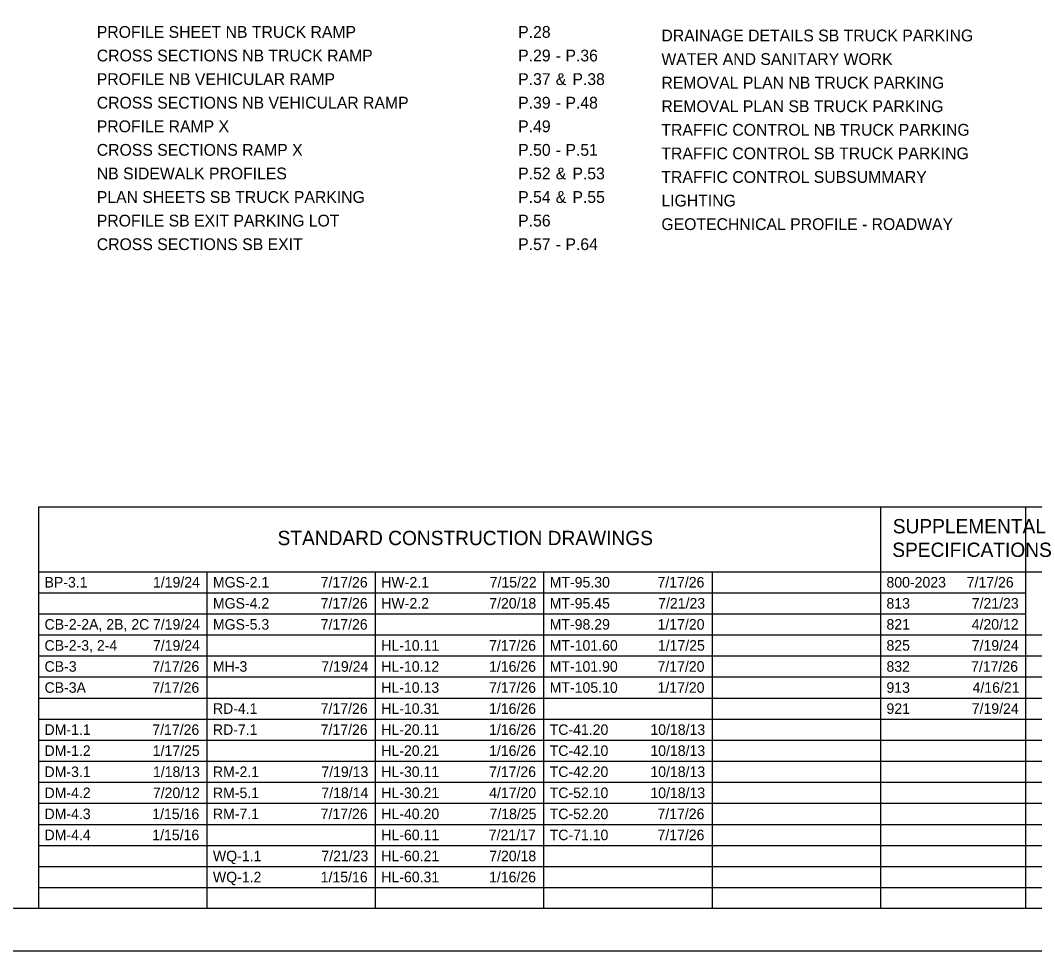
# Model space of a CAD drawing. Extents: x 0 to 34, y 0 to 22.
# Drawn here: x 9.93 to 21.98, y 0 to 11.05 of the extents above; entities that cross this region are included whole.
import ezdxf

# ---------------------------------------------------------------- set-up
doc = ezdxf.new("R2010")
doc.units = 0
for name, color, linetype in [('SH_Border', 7, 'Continuous'), ('SH_Cut_Line', 7, 'Continuous'), ('SH_Data', 7, 'Continuous'), ('SH_Text', 7, 'Continuous')]:
    doc.layers.add(name, color=color, linetype=linetype)

msp = doc.modelspace()

# ---------------------------------------------------------------- linework, layer by layer
at = {"layer": 'SH_Border'}
msp.add_lwpolyline([(1.5, 21.5), (33.5, 21.5), (33.5, 0.5), (1.5, 0.5)], close=True, dxfattribs=at)
at = {"layer": 'SH_Cut_Line'}
msp.add_lwpolyline([(0, 0), (34, 0), (34, 22), (0, 22)], close=True, dxfattribs=at)
at = {"layer": 'SH_Data'}
for p, q in [((10.15, 5.271), (23.6, 5.271)), ((10.15, 0.5), (10.15, 5.271)), ((20.15, 0.5), (20.15, 5.271)), ((21.875, 0.5), (21.875, 5.271)), ((10.15, 4.5), (23.6, 4.5)), ((12.15, 0.5), (12.15, 4.5)), ((14.15, 0.5), (14.15, 4.5)), ((16.15, 0.5), (16.15, 4.5)), ((18.15, 0.5), (18.15, 4.5)), ((10.15, 4.25), (21.875, 4.25)), ((10.15, 4), (21.875, 4)), ((10.15, 3.75), (23.6, 3.75)), ((10.15, 3.5), (23.6, 3.5)), ((10.15, 3.25), (23.6, 3.25)), ((10.15, 3), (23.6, 3)), ((10.15, 2.75), (23.6, 2.75)), ((10.15, 2.5), (23.6, 2.5)), ((10.15, 2.25), (23.6, 2.25)), ((10.15, 2), (23.6, 2)), ((10.15, 1.75), (23.6, 1.75)), ((10.15, 1.5), (23.6, 1.5)), ((10.15, 1.25), (23.6, 1.25)), ((10.15, 1), (23.6, 1)), ((10.15, 0.75), (23.6, 0.75))]:
    msp.add_line(p, q, dxfattribs=at)

# ---------------------------------------------------------------- texts
at = {"layer": 'SH_Text'}
for s, height, p in [('PROFILE SHEET NB TRUCK RAMP', 0.14, (10.839, 10.838)), ('P.28', 0.14, (15.844, 10.838)), ('DRAINAGE DETAILS SB TRUCK PARKING', 0.14, (17.545, 10.796)), ('CROSS SECTIONS NB TRUCK RAMP', 0.14, (10.839, 10.558)), ('P.29', 0.14, (15.844, 10.558)), (' - ', 0.14, (16.238, 10.558)), ('P.36', 0.14, (16.405, 10.558)), ('WATER AND SANITARY WORK', 0.14, (17.545, 10.516)), ('PROFILE NB VEHICULAR RAMP', 0.14, (10.839, 10.278)), ('P.37', 0.14, (15.844, 10.278)), (' & ', 0.14, (16.238, 10.278)), ('P.38', 0.14, (16.488, 10.278)), ('REMOVAL PLAN NB TRUCK PARKING', 0.14, (17.545, 10.236)), ('CROSS SECTIONS NB VEHICULAR RAMP', 0.14, (10.839, 9.998)), ('P.39', 0.14, (15.844, 9.998)), ('P.48', 0.14, (16.405, 9.998)), (' - ', 0.14, (16.238, 9.998)), ('REMOVAL PLAN SB TRUCK PARKING', 0.14, (17.545, 9.956)), ('PROFILE RAMP X', 0.14, (10.839, 9.718)), ('P.49', 0.14, (15.844, 9.718)), ('TRAFFIC CONTROL NB TRUCK PARKING', 0.14, (17.545, 9.676)), ('CROSS SECTIONS RAMP X', 0.14, (10.839, 9.438)), ('P.50', 0.14, (15.844, 9.438)), ('P.51', 0.14, (16.405, 9.438)), ('TRAFFIC CONTROL SB TRUCK PARKING', 0.14, (17.545, 9.396)), (' - ', 0.14, (16.238, 9.438)), ('NB SIDEWALK PROFILES', 0.14, (10.839, 9.158)), ('P.52', 0.14, (15.844, 9.158)), (' & ', 0.14, (16.238, 9.158)), ('P.53', 0.14, (16.488, 9.158)), ('TRAFFIC CONTROL SUBSUMMARY', 0.14, (17.545, 9.116)), ('PLAN SHEETS SB TRUCK PARKING', 0.14, (10.839, 8.878)), ('P.54', 0.14, (15.844, 8.878)), (' & ', 0.14, (16.238, 8.878)), ('P.55', 0.14, (16.488, 8.878)), ('LIGHTING ', 0.14, (17.545, 8.836)), ('PROFILE SB EXIT PARKING LOT', 0.14, (10.839, 8.598)), ('P.56', 0.14, (15.844, 8.598)), ('GEOTECHNICAL PROFILE - ROADWAY', 0.14, (17.545, 8.556)), ('CROSS SECTIONS SB EXIT', 0.14, (10.839, 8.318)), ('P.57', 0.14, (15.844, 8.318)), ('P.64', 0.14, (16.405, 8.318)), (' - ', 0.14, (16.238, 8.318)), ('SUPPLEMENTAL', 0.17, (20.293, 4.955)), ('STANDARD CONSTRUCTION DRAWINGS', 0.17, (12.986, 4.815)), ('SPECIFICATIONS', 0.17, (20.287, 4.675)), ('BP-3.1', 0.125, (10.218, 4.312)), ('1/19/24', 0.125, (11.506, 4.312)), ('MGS-2.1', 0.125, (12.218, 4.312)), ('7/17/26', 0.125, (13.498, 4.312)), ('HW-2.1', 0.125, (14.218, 4.312)), ('7/15/22', 0.125, (15.505, 4.312)), ('MT-95.30', 0.125, (16.218, 4.312)), ('7/17/26', 0.125, (17.498, 4.312)), ('800-2023', 0.125, (20.218, 4.312)), ('7/17/26', 0.125, (21.171, 4.312)), ('MGS-4.2', 0.125, (12.218, 4.062)), ('7/17/26', 0.125, (13.498, 4.062)), ('HW-2.2', 0.125, (14.218, 4.062)), ('7/20/18', 0.125, (15.5, 4.062)), ('MT-95.45', 0.125, (16.218, 4.062)), ('7/21/23', 0.125, (17.506, 4.062)), ('813', 0.125, (20.218, 4.062)), ('7/21/23', 0.125, (21.231, 4.062)), ('CB-2-2A, 2B, 2C', 0.125, (10.218, 3.812)), ('7/19/24', 0.125, (11.506, 3.812)), ('MGS-5.3', 0.125, (12.218, 3.812)), ('7/17/26', 0.125, (13.498, 3.812)), ('MT-98.29', 0.125, (16.218, 3.812)), ('1/17/20', 0.125, (17.499, 3.812)), ('821', 0.125, (20.218, 3.812)), ('4/20/12', 0.125, (21.23, 3.812)), ('CB-2-3, 2-4', 0.125, (10.218, 3.562)), ('7/19/24', 0.125, (11.506, 3.562)), ('HL-10.11', 0.125, (14.218, 3.562)), ('7/17/26', 0.125, (15.498, 3.562)), ('MT-101.60', 0.125, (16.218, 3.562)), ('1/17/25', 0.125, (17.503, 3.562)), ('825', 0.125, (20.218, 3.562)), ('7/19/24', 0.125, (21.231, 3.562)), ('CB-3', 0.125, (10.218, 3.312)), ('7/17/26', 0.125, (11.498, 3.312)), ('MH-3', 0.125, (12.218, 3.312)), ('7/19/24', 0.125, (13.506, 3.312)), ('HL-10.12', 0.125, (14.218, 3.312)), ('1/16/26', 0.125, (15.498, 3.312)), ('MT-101.90', 0.125, (16.218, 3.312)), ('7/17/20', 0.125, (17.499, 3.312)), ('832', 0.125, (20.218, 3.312)), ('7/17/26', 0.125, (21.223, 3.312)), ('CB-3A', 0.125, (10.218, 3.062)), ('7/17/26', 0.125, (11.498, 3.062)), ('HL-10.13', 0.125, (14.218, 3.062)), ('7/17/26', 0.125, (15.498, 3.062)), ('MT-105.10', 0.125, (16.218, 3.062)), ('1/17/20', 0.125, (17.499, 3.062)), ('913', 0.125, (20.218, 3.062)), ('4/16/21', 0.125, (21.241, 3.062)), ('RD-4.1', 0.125, (12.218, 2.812)), ('7/17/26', 0.125, (13.498, 2.812)), ('HL-10.31', 0.125, (14.218, 2.812)), ('1/16/26', 0.125, (15.498, 2.812)), ('921', 0.125, (20.218, 2.812)), ('7/19/24', 0.125, (21.231, 2.812)), ('DM-1.1', 0.125, (10.218, 2.562)), ('7/17/26', 0.125, (11.498, 2.562)), ('RD-7.1', 0.125, (12.218, 2.562)), ('7/17/26', 0.125, (13.498, 2.562)), ('HL-20.11', 0.125, (14.218, 2.562)), ('1/16/26', 0.125, (15.498, 2.562)), ('TC-41.20', 0.125, (16.218, 2.562)), ('10/18/13', 0.125, (17.414, 2.562)), ('DM-1.2', 0.125, (10.218, 2.312)), ('1/17/25', 0.125, (11.503, 2.312)), ('HL-20.21', 0.125, (14.218, 2.312)), ('1/16/26', 0.125, (15.498, 2.312)), ('TC-42.10', 0.125, (16.218, 2.312)), ('10/18/13', 0.125, (17.414, 2.312)), ('DM-3.1', 0.125, (10.218, 2.062)), ('1/18/13', 0.125, (11.506, 2.062)), ('RM-2.1', 0.125, (12.218, 2.062)), ('7/19/13', 0.125, (13.506, 2.062)), ('HL-30.11', 0.125, (14.218, 2.062)), ('7/17/26', 0.125, (15.498, 2.062)), ('TC-42.20', 0.125, (16.218, 2.062)), ('10/18/13', 0.125, (17.414, 2.062)), ('DM-4.2', 0.125, (10.218, 1.812)), ('7/20/12', 0.125, (11.505, 1.812)), ('RM-5.1', 0.125, (12.218, 1.812)), ('7/18/14', 0.125, (13.506, 1.812)), ('HL-30.21', 0.125, (14.218, 1.812)), ('4/17/20', 0.125, (15.499, 1.812)), ('TC-52.10', 0.125, (16.218, 1.812)), ('10/18/13', 0.125, (17.414, 1.812)), ('DM-4.3', 0.125, (10.218, 1.562)), ('1/15/16', 0.125, (11.498, 1.562)), ('RM-7.1', 0.125, (12.218, 1.562)), ('7/17/26', 0.125, (13.498, 1.562)), ('HL-40.20', 0.125, (14.218, 1.562)), ('7/18/25', 0.125, (15.503, 1.562)), ('TC-52.20', 0.125, (16.218, 1.562)), ('7/17/26', 0.125, (17.498, 1.562)), ('DM-4.4', 0.125, (10.218, 1.312)), ('1/15/16', 0.125, (11.498, 1.312)), ('HL-60.11', 0.125, (14.218, 1.312)), ('7/21/17', 0.125, (15.494, 1.312)), ('TC-71.10', 0.125, (16.218, 1.312)), ('7/17/26', 0.125, (17.498, 1.312)), ('WQ-1.1', 0.125, (12.218, 1.062)), ('7/21/23', 0.125, (13.506, 1.062)), ('HL-60.21', 0.125, (14.218, 1.062)), ('7/20/18', 0.125, (15.5, 1.062)), ('WQ-1.2', 0.125, (12.218, 0.812)), ('1/15/16', 0.125, (13.498, 0.812)), ('HL-60.31', 0.125, (14.218, 0.812)), ('1/16/26', 0.125, (15.498, 0.812))]:
    msp.add_text(s, height=height, dxfattribs=at).set_placement(p)

doc.saveas('drawing.dxf')
